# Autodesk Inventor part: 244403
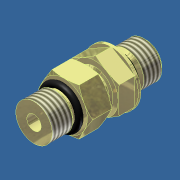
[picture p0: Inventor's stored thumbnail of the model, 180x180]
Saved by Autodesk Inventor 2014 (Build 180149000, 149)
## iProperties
Shininess: 20.0
Length Units: 11272
Angle Units: 11279
Time Units: 11290
Mass Units: 11286
Length Display Precision: 3
Angle Display Precision: 2
Company: Autodesk, Inc.
Created: 2001-10
Part Number: 244403
Material: Stainless Steel, 440C
Description: FITTING; ST-GG12-(SS)
Vendor: 0503-12-12
Document SubType Name: Modeling
Designer: Autodesk, Inc.
Density: 7.75 g/cm^3
Mass: 217.353 g
Surface Area: 130.425 cm^2
Volume: 28.0455 cm^3
Appearance: Stainless Steel
Density: 7.86
Volumn: 2.786291585014959
Area: 20.936420168139023
PropertySet Name: Model Information
Control State: 0
Master: False
Checked Out: False
Last Check In By: JT
Last Check In Date: 2003-06-20
MODEL - 1: ---
MODEL - 2: ---
RAW MATERIAL: --------
SCALE:: 1=??
SIZE: 00 x 00 x 00
SUB-ASSY - 1: ------
SUB-ASSY - 1 - QUA: 1
SUB-ASSY - 2: ------
SUB-ASSY - 2 - QUA: 1
SYM. TO:: N/A
TEMPLATE CREATION: -- / __-__-__
Title: FITTING; ST-GG12-(SS)
Author: Autodesk, Inc.
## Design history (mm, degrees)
derived "ST-GG.ipt"
body "Solid1"
tag "TaggingFeature2"
feature "Solid1::ST-GG.ipt" dims "ScaleForDerivedMember" = 10
